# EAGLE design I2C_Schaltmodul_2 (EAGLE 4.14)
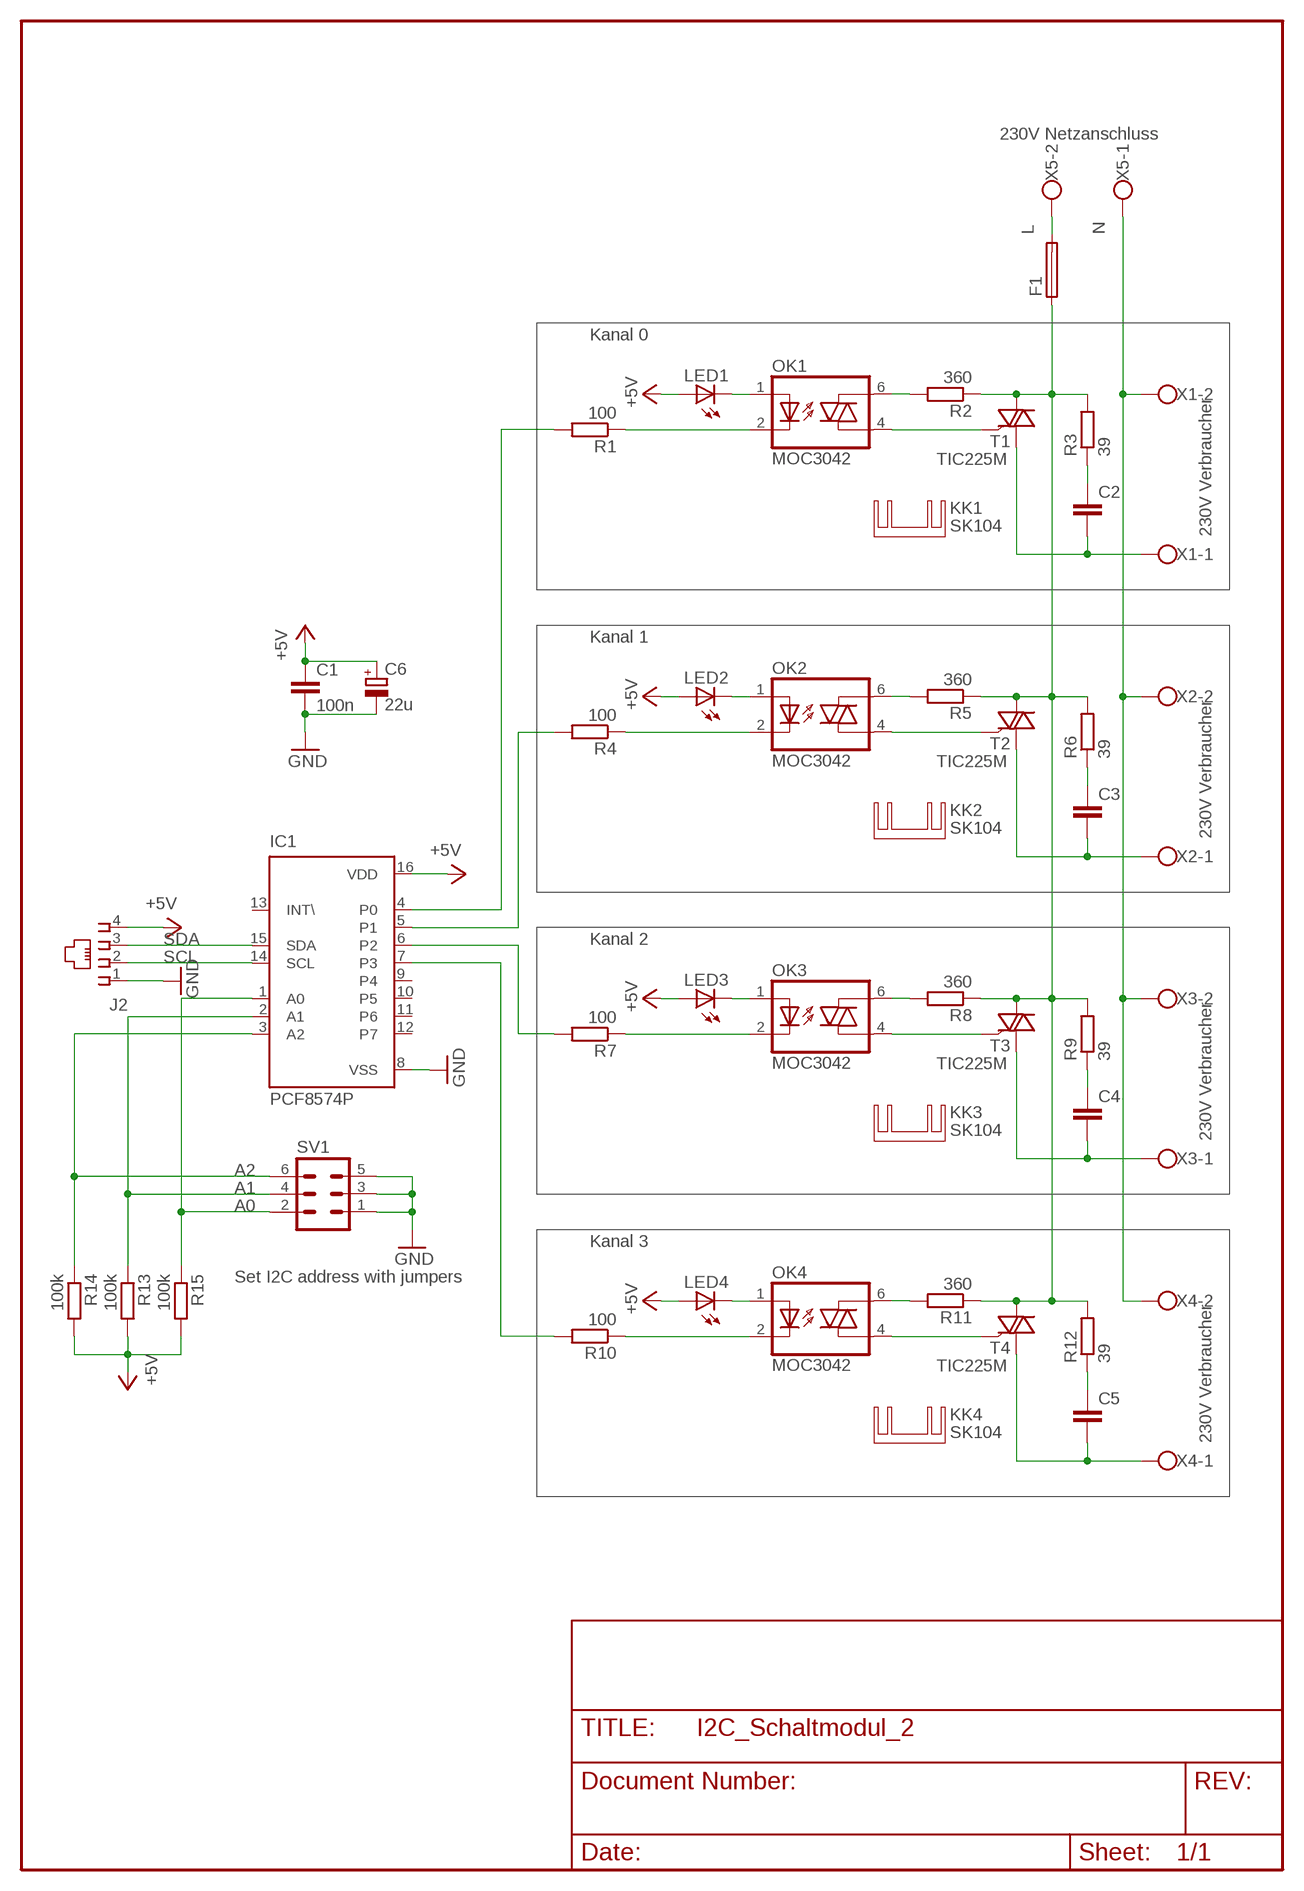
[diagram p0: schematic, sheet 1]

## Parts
C1  100n  C-EU025-025X050  [C025-025X050]
C2  C-EU102-043X133  [C102-043X133]
C3  C-EU102-043X133  [C102-043X133]
C4  C-EU102-043X133  [C102-043X133]
C5  C-EU102-043X133  [C102-043X133]
C6  22u  CPOL-EUE2.5-5  [E2,5-5]
F1  SH25  [SH25]
IC1  PCF8574P  [DIL16]
J2  215875-3  [215875-3]
KK1  SK104  [SK104]
KK2  SK104  [SK104]
KK3  SK104  [SK104]
KK4  SK104  [SK104]
LED1  LED3MM  [LED3MM]
LED2  LED3MM  [LED3MM]
LED3  LED3MM  [LED3MM]
LED4  LED3MM  [LED3MM]
OK1  MOC3042  IL420  [DIL06]
OK2  MOC3042  IL420  [DIL06]
OK3  MOC3042  IL420  [DIL06]
OK4  MOC3042  IL420  [DIL06]
R1  100  R-EU_0207/10  [0207/10]
R2  360  R-EU_0207/10  [0207/10]
R3  39  R-EU_0411/15  [0411/15]
R4  100  R-EU_0207/10  [0207/10]
R5  360  R-EU_0207/10  [0207/10]
R6  39  R-EU_0411/15  [0411/15]
R7  100  R-EU_0207/10  [0207/10]
R8  360  R-EU_0207/10  [0207/10]
R9  39  R-EU_0411/15  [0411/15]
R10  100  R-EU_0207/10  [0207/10]
R11  360  R-EU_0207/10  [0207/10]
R12  39  R-EU_0411/15  [0411/15]
R13  100k  R-EU_0207/10  [0207/10]
R14  100k  R-EU_0207/10  [0207/10]
R15  100k  R-EU_0207/10  [0207/10]
SV1  MA03-2  [MA03-2]
T1  TIC225M  TIC225S  [TO220DS]
T2  TIC225M  TIC225S  [TO220DS]
T3  TIC225M  TIC225S  [TO220DS]
T4  TIC225M  TIC225S  [TO220DS]
X1  W237-102  [W237-102]
X2  W237-102  [W237-102]
X3  W237-102  [W237-102]
X4  W237-102  [W237-102]
X5  W237-102  [W237-102]

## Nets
+5V: C1.1 C6.+ IC1.16(VDD) J2.4 LED1.A LED2.A LED3.A LED4.A R13.2 R14.2 R15.2
A0: IC1.1(A0) R15.1 SV1.2
A1: IC1.2(A1) R13.1 SV1.4
A2: IC1.3(A2) R14.1 SV1.6
GND: C1.2 C6.- IC1.8(VSS) J2.1 SV1.1 SV1.3 SV1.5
L: F1.2 X5.2
N: X1.2 X2.2 X3.2 X4.2 X5.1
N$1: IC1.4(P0) R1.2
N$2: LED1.K(C) OK1.1(A)
N$3: OK1.6(A2) R2.2
N$4: IC1.5(P1) R4.2
N$5: OK1.4(A1) T1.G
N$6: C2.1 R3.1
N$7: OK1.2(C) R1.1
N$8: OK3.6(A2) R8.2
N$9: OK2.6(A2) R5.2
N$10: OK2.4(A1) T2.G
N$11: C3.2 T2.A1 X2.1
N$12: C3.1 R6.1
N$13: C2.2 T1.A1 X1.1
N$14: LED2.K(C) OK2.1(A)
N$15: OK2.2(C) R4.1
N$16: OK3.4(A1) T3.G
N$17: C4.2 T3.A1 X3.1
N$18: C4.1 R9.1
N$19: IC1.6(P2) R7.2
N$20: LED3.K(C) OK3.1(A)
N$21: OK3.2(C) R7.1
N$22: OK4.6(A2) R11.2
N$23: OK4.4(A1) T4.G
N$24: C5.2 T4.A1 X4.1
N$25: C5.1 R12.1
N$26: IC1.7(P3) R10.2
N$27: LED4.K(C) OK4.1(A)
N$28: OK4.2(C) R10.1
N$100: F1.1 R2.1 R3.2 R5.1 R6.2 R8.1 R9.2 R11.1 R12.2 T1.A2 T2.A2 T3.A2 T4.A2
SCL: IC1.14(SCL) J2.2
SDA: IC1.15(SDA) J2.3
Unconnected: IC1.9(P4) IC1.10(P5) IC1.11(P6) IC1.12(P7) IC1.13(INT\)

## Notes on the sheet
- 230V Netzanschluss
- Kanal 0
- 230V Verbraucher
- Kanal 1
- 230V Verbraucher
- Kanal 2
- 230V Verbraucher
- Kanal 3
- Set I2C address with jumpers
- 230V Verbraucher

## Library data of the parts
C1-C5 = rcl:C-EU: CAPACITOR, European symbol
C6 = rcl:CPOL-EU: POLARIZED CAPACITOR, European symbol
F1 = fuse:SH25: FUSE HOLDER
IC1 = micro-philips:PCF8574: I2C-Bus I/O DEVICE
J2 = con-amp:215875-3: AMP connector
KK1-KK4 = heatsink:SK104: HEATSINK
LED1-LED4 = led:LED: LED
OK1-OK4 = optocoupler:IL420: SIEMENS OPTO COUPLER
R1-R15 = rcl:R-EU_: RESISTOR, European symbol
SV1 = con-lstb:MA03-2: PIN HEADER
T1-T4 = triac:TIC225S: TRIAC
X1-X5 = con-wago-500:W237-102: WAGO SCREW CLAMP

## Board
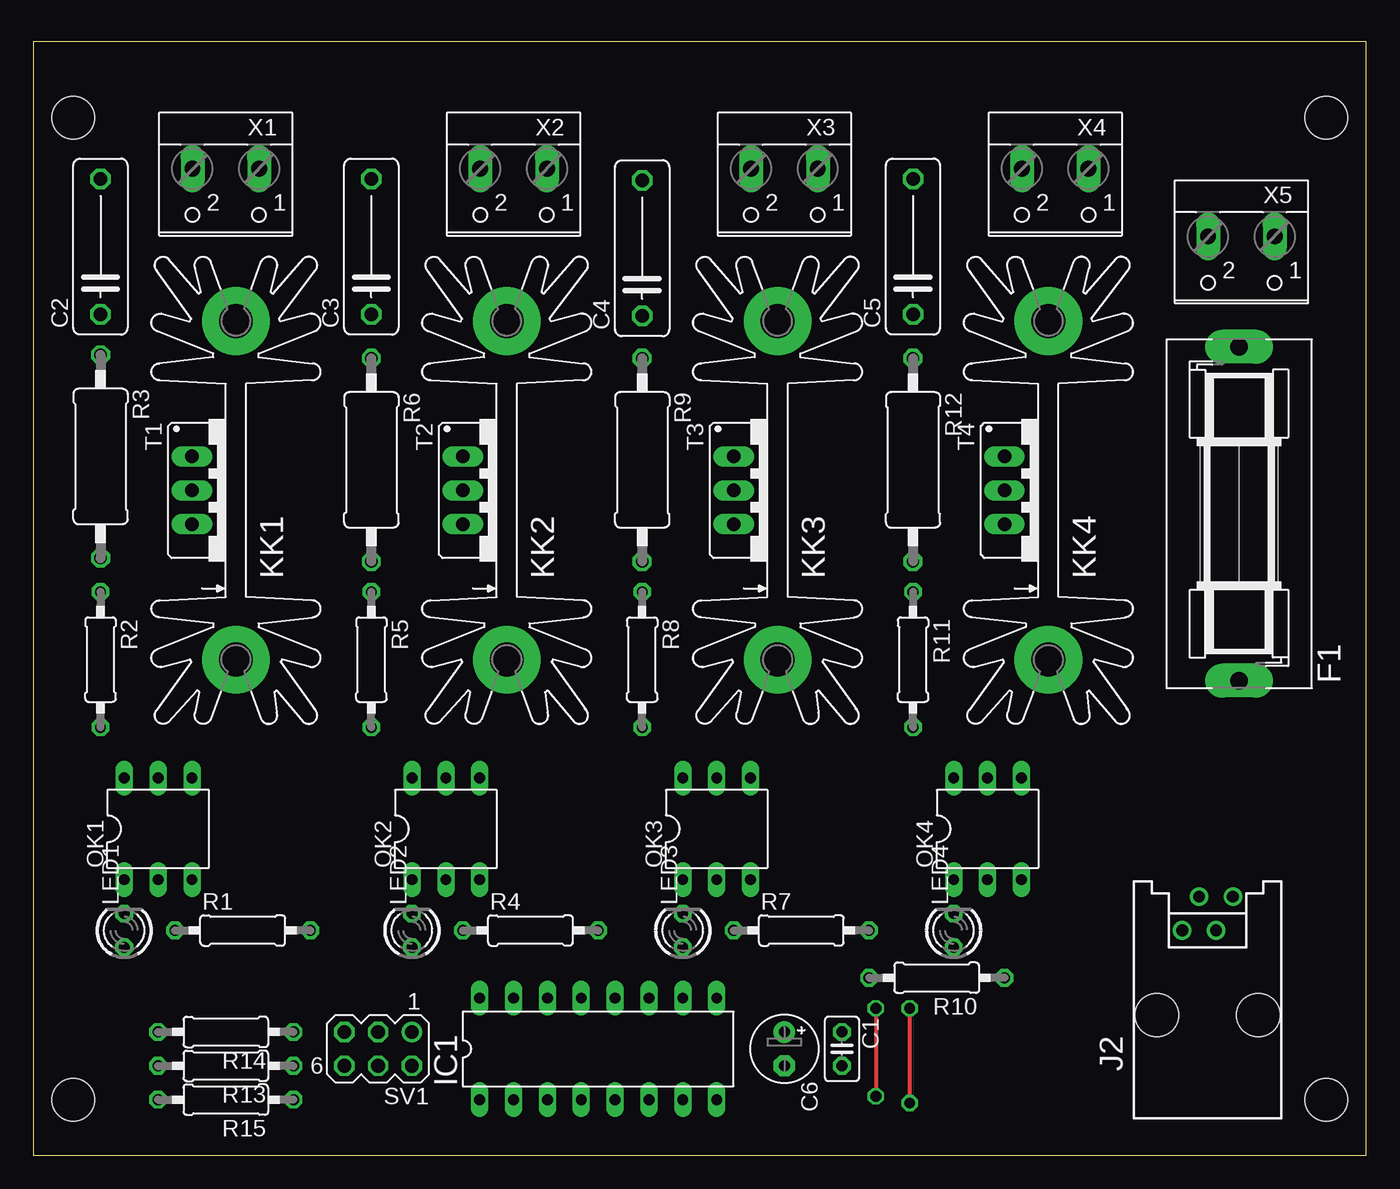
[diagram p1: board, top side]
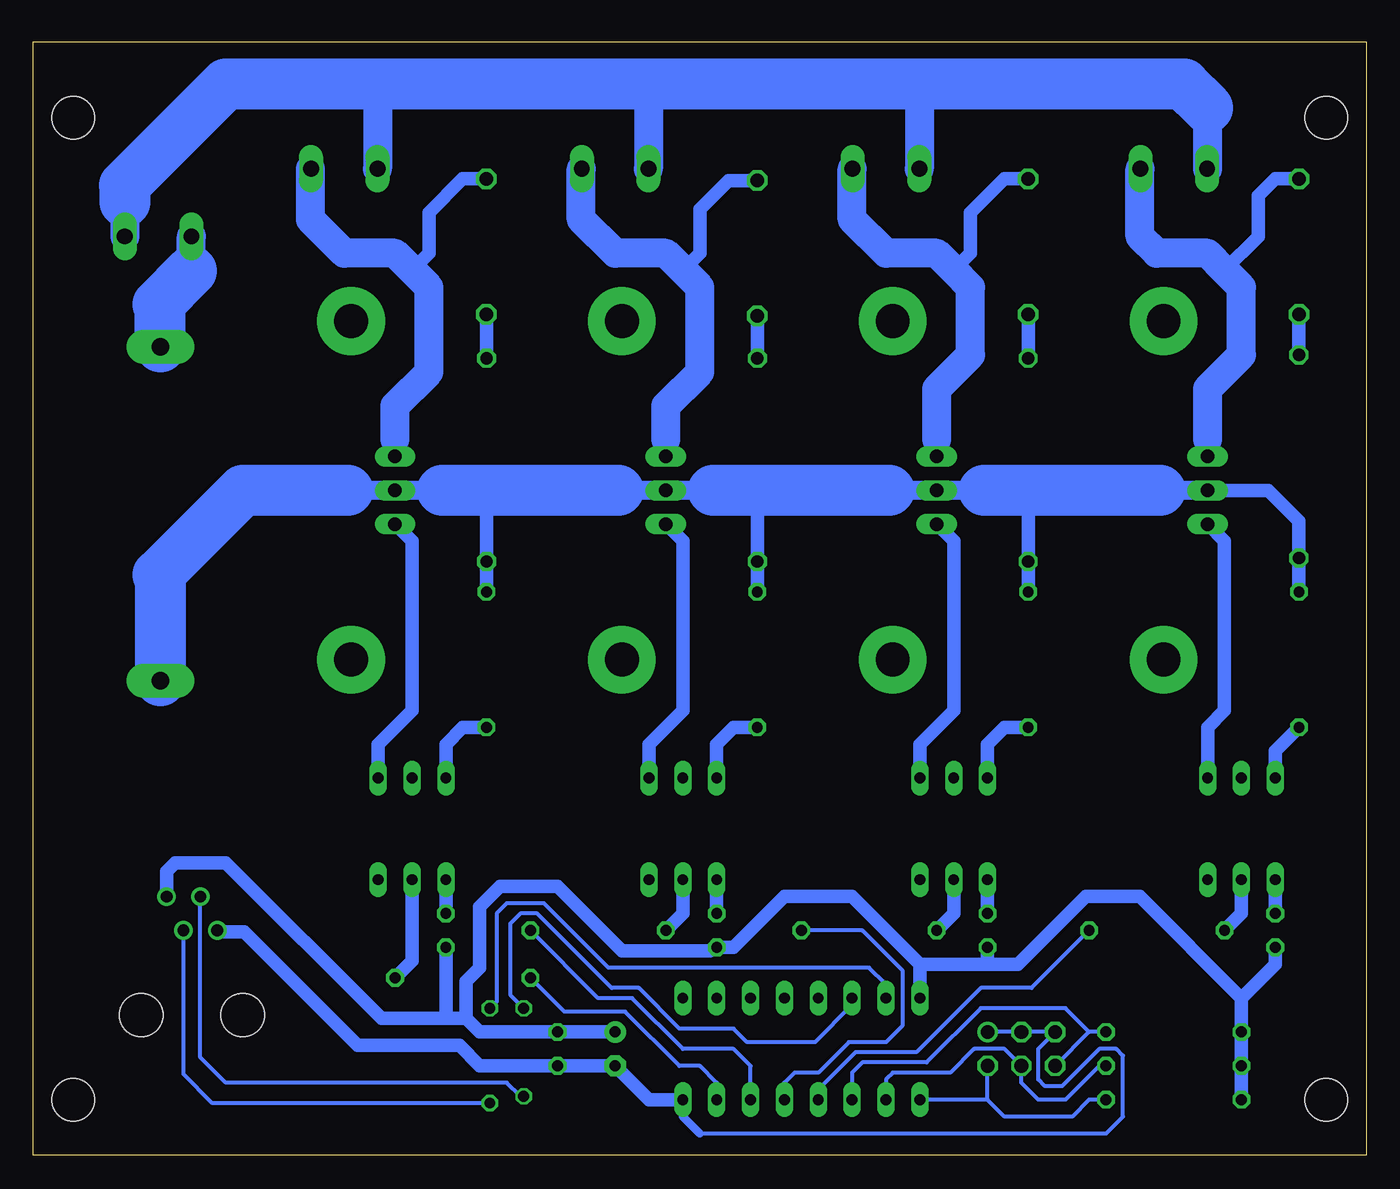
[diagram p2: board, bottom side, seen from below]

Size 100 x 83.56 mm. Coordinates in mm from the lower left corner, seen from the top.
Outline: 0,0 100,0 100,83.56 0,83.56 0,0
Copper layers (1*16): Top 0.035mm / dielectric 1.5mm / Bottom 0.035mm
Design rules "default": minimum track width 12mil, minimum drill 24mil, track to track 12mil, track to pad 12mil, pad to pad 12mil, via to via 12mil, smd to smd 8mil, copper to edge 40mil, drill to drill 8mil, minimum pad ring 10mil, minimum via ring 8mil, stop-mask expansion 4mil, vias tented up to drill 0mil, thermal gap 10mil
Holes 3.2 mm at 3.01,77.85 3.01,4.19 96.99,4.19 96.99,77.85

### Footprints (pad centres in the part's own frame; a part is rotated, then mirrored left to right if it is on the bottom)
C025-025X050 = drill 0.813 octagon: 1 -1.27,0; 2 1.27,0
C102-043X133 = drill 1.016 octagon: 1 -5.08,0; 2 5.08,0
E2,5-5 = drill 0.813 pad 1.6 round: + -1.27,0 | drill 0.813 pad 1.6 octagon: - 1.27,0
SH25 = drill 1.321 pad 2.54 long: 1 -12.522,0; 2 12.522,0
DIL16 = drill 0.813 long: 1 -8.89,-3.81; 2 -6.35,-3.81; 3 -3.81,-3.81; 4 -1.27,-3.81; 5 1.27,-3.81; 6 3.81,-3.81; 7 6.35,-3.81; 8 8.89,-3.81; 9 8.89,3.81; 10 6.35,3.81; 11 3.81,3.81; 12 1.27,3.81; 13 -1.27,3.81; 14 -3.81,3.81; 15 -6.35,3.81; 16 -8.89,3.81
215875-3 = drill 0.889 round: 1 -1.905,6.35; 2 -0.635,8.89; 3 0.635,6.35; 4 1.905,8.89 | hole 3.251: -3.81,0; 3.81,0
SK104 = drill 2.54 pad 5.08 round: A2,5 -12.7,-0.762; B2,5 12.7,-0.762
LED3MM = drill 0.813 octagon: A -1.27,0; K 1.27,0
DIL06 = drill 0.813 long: 1 -2.54,-3.81; 2 0,-3.81; 3 2.54,-3.81; 4 2.54,3.81; 5 0,3.81; 6 -2.54,3.81
0207/10 = drill 0.813 octagon: 1 -5.08,0; 2 5.08,0
0411/15 = drill 0.914 octagon: 1 -7.62,0; 2 7.62,0
MA03-2 = drill 1.016 round: 1 -2.54,-1.27 | drill 1.016 octagon: 2 -2.54,1.27; 3 0,-1.27; 4 0,1.27; 5 2.54,-1.27; 6 2.54,1.27
TO220DS = drill 1.016 long: A1 -2.54,-2.54; A2 0,-2.54; G 2.54,-2.54
W237-102 = drill 1.194 long: 1 -2.5,-1.27; 2 2.5,-1.27

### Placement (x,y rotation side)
C1  60.67,8 270 top
C2  5.04,68.19 90 top
C3  25.36,68.19 90 top
C4  45.68,68.07 90 top
C5  66,68.19 90 top
C6  56.35,8 270 top
F1  90.47,48.16 90 top
IC1  42.38,8 0 top
J2  88.1,10.54 0 top
KK1  14.44,49.91 90 top
KK2  34.76,49.91 90 top
KK3  55.08,49.91 90 top
KK4  75.4,49.91 90 top
LED1  6.82,16.89 90 top
LED2  28.41,16.89 90 top
LED3  48.73,16.89 90 top
LED4  69.05,16.89 90 top
OK1  9.36,24.51 0 top
OK2  30.95,24.51 0 top
OK3  51.27,24.51 0 top
OK4  71.59,24.51 0 top
R1  15.71,16.89 0 top
R2  5.04,37.21 270 top
R3  5.04,52.45 270 top
R4  37.3,16.89 0 top
R5  25.36,37.21 270 top
R6  25.36,52.19 270 top
R7  57.62,16.89 0 top
R8  45.68,37.21 270 top
R9  45.68,52.19 270 top
R10  67.78,13.33 180 top
R11  66,37.21 270 top
R12  66,52.19 270 top
R13  14.44,6.73 180 top
R14  14.44,9.27 180 top
R15  14.44,4.19 180 top
SV1  25.87,8 180 top
T1  14.44,49.91 270 top
T2  34.76,49.91 270 top
T3  55.08,49.91 270 top
T4  75.4,49.91 270 top
X1  14.44,72.77 180 top
X2  36.03,72.77 180 top
X3  56.35,72.77 180 top
X4  76.67,72.77 180 top
X5  90.64,67.69 180 top

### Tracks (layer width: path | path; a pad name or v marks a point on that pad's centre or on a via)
+5V
  Bottom 1.016: LED1.A 6.82,14.35 9.36,11.81 | R15.2 R13.2 R14.2 9.36,11.81 | 9.36,11.81 16.98,19.43 21.04,19.43 26.12,14.35 28.41,14.35 | 28.41,14.35 LED2.A | 28.41,14.35 33.49,14.35 | 33.49,14.35 IC1.16 | 33.49,14.35 38.57,19.43 43.65,19.43 47.46,15.62 LED3.A 48.98,15.62 49.24,15.36 55.84,15.36 60.67,20.19 64.99,20.19 66.51,18.66 66.51,14.09 67.53,13.08 67.53,10.28 | C6.+ C1.1 66.51,9.27 67.53,10.28 | 67.53,10.28 69.05,10.28 LED4.A | 67.53,10.28 73.88,10.28 85.56,21.97 89.37,21.97 90,21.33 J2.4
A0
  Bottom 0.305: R15.1 20.79,4.19 22.06,2.92 27.14,2.92 28.41,4.19 | 28.41,4.19 SV1.2 | 28.41,4.19 IC1.1
A1
  Bottom 0.305: R13.1 20.03,6.73 22.57,4.19 24.6,4.19 25.87,5.46 SV1.4 27.14,8 29.43,8 31.2,6.22 35.52,6.22 36.03,5.71 IC1.2
A2
  Bottom 0.305: R14.1 20.79,9.27 | 20.79,9.27 SV1.6 | IC1.3 38.57,6.22 37.81,6.98 32.98,6.98 28.92,11.04 22.57,11.04 20.79,9.27
GND
  Bottom 0.305: 50,1.65 19.52,1.65 18.25,2.92 18.25,7.49 18.76,8 20.03,8 22.82,5.2 24.09,5.2 24.6,5.71 24.6,8 SV1.5 SV1.3 SV1.1
  Bottom 0.61: IC1.8 51.27,2.92 50,1.65
  Bottom 1.016: IC1.8 53.81,4.19 C6.- C1.2 66.51,6.73 68.03,8.25 75.65,8.25 84.16,16.76 86.19,16.76 J2.1
L
  Bottom 2.184: 88.14,66.38 X5.2
  Bottom 3.81: 88.14,66.38 90.64,63.88 90.47,63.71 F1.2
N
  Bottom 0.61: X1.2 11.9,74.04
  Bottom 2.184: 93.14,71.54 X5.1 | 11.9,74.04 11.9,78.61 | 53.81,80.39 53.81,80.13 53.85,80.09 X3.2 | X4.2 74.17,80.35 74.13,80.39 | 33.49,80.39 33.49,80.13 33.53,80.09 X2.2
  Bottom 3.81: 93.14,71.54 93.14,72.73 93.18,72.77 85.56,80.39 74.13,80.39 53.81,80.39 33.49,80.39 13.68,80.39 11.9,78.61
N$1
  Bottom 0.305: R1.2 25.11,12.57 28.92,12.57 33.74,7.74 38.32,7.74 41.11,4.95 IC1.4
N$2
  Bottom 1.016: LED1.K OK1.1
N$3
  Bottom 1.016: R2.2 6.82,30.35 OK1.6
N$4
  Bottom 0.305: R4.2 37.81,16.89 34.76,13.84 34.76,9.77 36.03,8.5 38.82,8.5 41.11,6.22 42.89,6.22 43.65,5.46 IC1.5
N$5
  Bottom 1.016: OK1.4 11.9,32.13 10.63,33.4 10.63,46.1 T1.G
N$6
  Bottom 1.016: R3.1 C2.1
N$7
  Bottom 1.016: OK1.2 9.36,18.16 R1.1
N$8
  Bottom 1.016: R8.2 47.46,32.13 48.73,30.86 OK3.6
N$9
  Bottom 1.016: R5.2 27.14,32.13 28.41,30.86 OK2.6
N$10
  Bottom 1.016: OK2.4 33.49,30.86 30.95,33.4 30.95,46.1 T2.G
N$11
  Bottom 0.61: 38.57,74.04 X2.1
  Bottom 1.016: 30.95,66.42 29.68,67.69 29.68,70.73 27.14,73.27 C3.2
  Bottom 1.422: T2.A1 32.22,53.72
  Bottom 2.184: 32.22,53.72 32.22,57.53 29.68,60.07 29.68,65.15 30.95,66.42 32.22,67.69 36.03,67.69 38.57,70.23 38.57,74.04
N$12
  Bottom 1.016: R6.1 C3.1
N$13
  Bottom 0.61: 16.98,74.04 X1.1
  Bottom 1.016: 10.63,66.42 8.09,68.96 8.09,72 6.82,73.27 C2.2
  Bottom 1.422: T1.A1 11.9,53.72
  Bottom 2.184: 11.9,53.72 11.9,57.53 9.36,60.07 9.36,65.15 10.63,66.42 11.9,67.69 15.71,67.69 16.98,68.96 16.98,74.04
N$14
  Bottom 1.016: LED2.K OK2.1
N$15
  Bottom 1.016: OK2.2 30.95,18.16 R4.1
N$16
  Bottom 1.016: OK3.4 53.81,30.86 51.27,33.4 51.27,46.1 T3.G
N$17
  Bottom 0.61: 58.89,74.04 X3.1
  Bottom 1.016: 51.27,66.42 50,67.69 50,70.99 47.84,73.15 C4.2
  Bottom 1.422: T3.A1 52.54,53.72
  Bottom 2.184: 52.54,53.72 52.54,56.26 50,58.8 50,65.15 51.27,66.42 52.54,67.69 56.35,67.69 58.89,70.23 58.89,74.04
N$18
  Bottom 1.016: R9.1 C4.1
N$19
  Bottom 0.305: R7.2 57.62,11.81 55.08,11.81 51.27,8 47.46,8 46.19,6.73 IC1.6
N$20
  Bottom 1.016: LED3.K OK3.1
N$21
  Bottom 1.016: OK3.2 51.27,18.16 R7.1
N$22
  Bottom 1.016: R11.2 67.78,32.13 69.05,30.86 OK4.6
N$23
  Bottom 1.016: OK4.4 74.13,30.86 71.59,33.4 71.59,46.1 T4.G
N$24
  Bottom 0.61: 79.21,74.04 X4.1
  Bottom 1.016: 71.59,66.42 70.32,67.69 70.32,70.73 67.78,73.27 C5.2
  Bottom 1.422: T4.A1 72.86,53.72
  Bottom 2.184: 72.86,53.72 72.86,56.26 70.32,58.8 70.32,65.15 71.59,66.42 72.86,67.69 76.67,67.69 79.21,70.23 79.21,74.04
N$25
  Bottom 1.016: R12.1 C5.1
N$26
  Bottom 0.305: IC1.7 48.73,5.46 50,6.73 51.52,6.73 55.59,10.79 60.16,10.79 R10.2
N$27
  Bottom 1.016: LED4.K OK4.1
N$28
  Bottom 1.016: OK4.2 71.59,14.6 R10.1
N$100
  Bottom 1.016: T1.A2 7.33,49.91 5.04,47.62 R3.2 R2.1 | R5.1 R6.2 25.36,49.91 | R8.1 R9.2 45.68,49.91 | R11.1 R12.2 66,49.91
  Bottom 1.422: 76.42,49.91 T4.A2 69.3,49.91 | 56.1,49.91 T3.A2 48.98,49.91 | 35.78,49.91 T2.A2 28.66,49.91 | T1.A2 15.46,49.91
  Bottom 3.81: 76.42,49.91 84.29,49.91 90.64,43.56 90.47,43.39 F1.1 | 69.3,49.91 66,49.91 56.1,49.91 | 35.78,49.91 45.68,49.91 48.98,49.91 | 15.46,49.91 25.36,49.91 28.66,49.91
SCL  (via drill 0.81)
  Top 0.305: v63.21,11.04 v63.21,4.44
  Bottom 0.305: J2.2 87.47,7.36 85.56,5.46 64.48,5.46 63.46,4.44 v63.21,4.44 | IC1.14 38.57,11.3 41.36,8.5 46.44,8.5 47.46,9.52 51.52,9.52 54.57,12.57 56.6,12.57 62.19,18.16 63.46,18.16 64.22,17.39 64.22,12.06 v63.21,11.04
SDA  (via drill 0.81)
  Top 0.305: v65.75,11.04 v65.75,3.93
  Bottom 0.305: J2.3 88.73,6.09 86.58,3.93 v65.75,3.93 | IC1.15 36.03,12.82 37.3,14.09 56.86,14.09 61.68,18.92 64.48,18.92 65.24,18.16 65.24,11.55 v65.75,11.04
